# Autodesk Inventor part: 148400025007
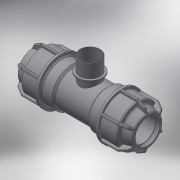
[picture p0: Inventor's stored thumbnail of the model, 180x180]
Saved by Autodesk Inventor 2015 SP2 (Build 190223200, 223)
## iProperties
Created: 2017-08
Part Number: 148400025007
Material: Generic
Description: PLASSON L.14 TEE MALE ADAPTOR (SILVER) 25-3/4"-25
Document SubType Name: Modeling
Designer: KIM
Density: 1 g/cm^3
Appearance: Default
Author: KIM
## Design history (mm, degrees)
derived "148400.ipt"
feature "Solid1::148400.ipt"
feature "Solid2::148400.ipt"
tag "TaggingFeature1"
body "Solid1"
body "Solid2"
other parameters: "d1" = 25, "d2" = 48, "d4" = 15 deg, "d5" = 31.68, "d6" = 10.4544, "d16" = 25.5, "d17" = 2.4, "d24" = 2.4, "d25" = 45, "d26" = 37.5, "d27" = 2.4, "d28" = 135 deg, "d29" = 1.44, "d31" = 1.25, "d46" = 150 deg, "d49" = 2.5, "d50" = 0, "d58" = 0.75, "d61" = 360 deg, "d63" = 22.5, "d64" = 62, "d80" = 36, "d81" = 2, "d84" = 2.4, "d94" = 47, "d96" = 26.441, "d108" = 0.75, "d111" = 0, "d114" = 31.7292, "d115" = 18, "d116" = 1.8, "d117" = 26.441, "d_" = 25, "R_" = 26.441, "H_" = 124, "l_" = 48, "l_2" = 18, "A_" = 47
